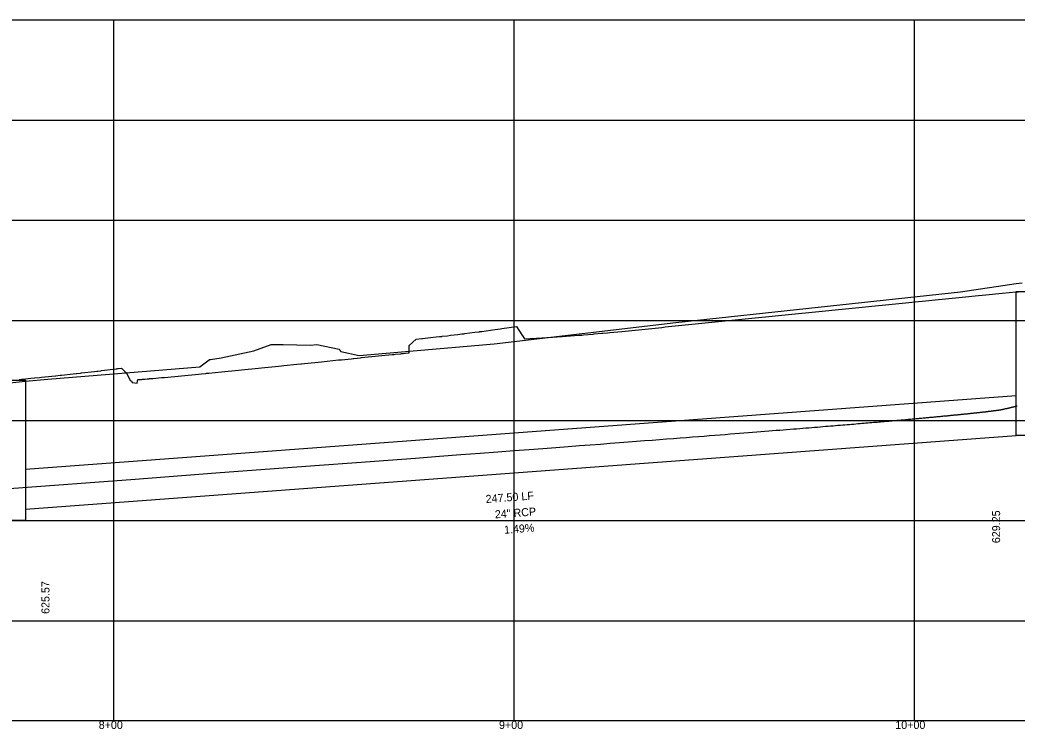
# Model space of a CAD drawing. Extents: x 2254979 to 2278074, y 13790855 to 13792793.
# Drawn here: x 2260737.2 to 2260986.3, y 13792139.4 to 13792316.4 of the extents above; entities that cross this region are included whole.
import ezdxf

# ---------------------------------------------------------------- set-up
doc = ezdxf.new("R2010")
doc.units = 0
for name, color, linetype in [('blank4', 7, 'Continuous'), ('D_DRN_PROF_HGL', 7, 'Continuous'), ('D_PROF_1', 7, 'Continuous'), ('D_PROF_NOTES_1', 7, 'Continuous'), ('Default', 7, 'Continuous'), ('Drain_PipeInside', 7, 'Continuous'), ('E_Terrain', 7, 'Continuous'), ('Inlet', 7, 'Continuous'), ('z - Construction', 7, 'Continuous')]:
    doc.layers.add(name, color=color, linetype=linetype)

msp = doc.modelspace()

# ---------------------------------------------------------------- linework, layer by layer
at = {"layer": 'blank4'}
msp.add_lwpolyline([(2259960.69, 13792141.44), (2259960.69, 13792316.44), (2261351.48, 13792316.44), (2261351.48, 13792141.44)], close=True, dxfattribs=at)
at = {"layer": 'D_DRN_PROF_HGL'}
msp.add_lwpolyline([(2260734.57, 13792199.49), (2260765.97, 13792201.83), (2260786.15, 13792203.34), (2260800.68, 13792204.43), (2260812.02, 13792205.27), (2260821.31, 13792205.97), (2260829.17, 13792206.56), (2260835.98, 13792207.07), (2260841.98, 13792207.52), (2260847.34, 13792207.93), (2260852.18, 13792208.29), (2260856.59, 13792208.63), (2260860.64, 13792208.93), (2260864.38, 13792209.21), (2260867.85, 13792209.48), (2260871.09, 13792209.72), (2260874.13, 13792209.96), (2260876.99, 13792210.17), (2260879.68, 13792210.38), (2260882.23, 13792210.57), (2260884.65, 13792210.76), (2260886.95, 13792210.93), (2260889.14, 13792211.1), (2260891.24, 13792211.26), (2260893.24, 13792211.42), (2260895.16, 13792211.56), (2260897, 13792211.71), (2260898.77, 13792211.84), (2260900.47, 13792211.97), (2260902.11, 13792212.1), (2260903.69, 13792212.22), (2260905.21, 13792212.34), (2260906.69, 13792212.46), (2260908.12, 13792212.57), (2260909.5, 13792212.68), (2260910.84, 13792212.78), (2260912.13, 13792212.88), (2260913.39, 13792212.98), (2260914.62, 13792213.08), (2260915.81, 13792213.17), (2260916.96, 13792213.26), (2260918.09, 13792213.35), (2260919.18, 13792213.44), (2260920.25, 13792213.52), (2260921.29, 13792213.6), (2260922.3, 13792213.68), (2260923.29, 13792213.76), (2260924.26, 13792213.84), (2260925.2, 13792213.91), (2260926.12, 13792213.99), (2260927.02, 13792214.06), (2260927.9, 13792214.13), (2260928.75, 13792214.2), (2260929.6, 13792214.27), (2260930.42, 13792214.33), (2260931.22, 13792214.4), (2260932.01, 13792214.46), (2260932.78, 13792214.52), (2260933.54, 13792214.59), (2260934.28, 13792214.65), (2260935.01, 13792214.7), (2260935.72, 13792214.76), (2260936.42, 13792214.82), (2260937.11, 13792214.88), (2260937.78, 13792214.93), (2260938.44, 13792214.99), (2260939.09, 13792215.04), (2260939.73, 13792215.09), (2260940.35, 13792215.14), (2260940.97, 13792215.19), (2260941.57, 13792215.24), (2260942.17, 13792215.29), (2260942.75, 13792215.34), (2260943.32, 13792215.39), (2260943.89, 13792215.44), (2260944.44, 13792215.48), (2260944.99, 13792215.53), (2260945.53, 13792215.57), (2260946.05, 13792215.62), (2260946.57, 13792215.66), (2260947.08, 13792215.7), (2260947.59, 13792215.75), (2260948.08, 13792215.79), (2260948.57, 13792215.83), (2260949.05, 13792215.87), (2260949.53, 13792215.91), (2260949.99, 13792215.95), (2260950.45, 13792215.99), (2260950.91, 13792216.03), (2260951.35, 13792216.07), (2260951.79, 13792216.1), (2260952.22, 13792216.14), (2260952.65, 13792216.18), (2260953.07, 13792216.21), (2260953.49, 13792216.25), (2260953.9, 13792216.29), (2260954.3, 13792216.32), (2260954.7, 13792216.35), (2260955.09, 13792216.39), (2260955.48, 13792216.42), (2260955.86, 13792216.46), (2260956.24, 13792216.49), (2260956.61, 13792216.52), (2260956.98, 13792216.55), (2260957.34, 13792216.59), (2260957.7, 13792216.62), (2260958.05, 13792216.65), (2260958.4, 13792216.68), (2260958.74, 13792216.71), (2260959.08, 13792216.74), (2260959.42, 13792216.77), (2260959.75, 13792216.8), (2260960.07, 13792216.83), (2260960.4, 13792216.86), (2260960.72, 13792216.89), (2260961.03, 13792216.92), (2260961.34, 13792216.94), (2260961.65, 13792216.97), (2260961.95, 13792217), (2260962.25, 13792217.03), (2260962.55, 13792217.05), (2260962.84, 13792217.08), (2260963.13, 13792217.11), (2260963.41, 13792217.13), (2260963.7, 13792217.16), (2260963.97, 13792217.18), (2260964.25, 13792217.21), (2260964.52, 13792217.24), (2260964.79, 13792217.26), (2260965.06, 13792217.29), (2260965.32, 13792217.31), (2260965.58, 13792217.33), (2260965.84, 13792217.36), (2260966.09, 13792217.38), (2260966.34, 13792217.41), (2260966.59, 13792217.43), (2260966.83, 13792217.45), (2260967.08, 13792217.48), (2260967.32, 13792217.5), (2260967.55, 13792217.52), (2260967.79, 13792217.54), (2260968.02, 13792217.57), (2260968.25, 13792217.59), (2260968.48, 13792217.61), (2260968.7, 13792217.63), (2260968.92, 13792217.65), (2260969.14, 13792217.67), (2260969.36, 13792217.7), (2260969.57, 13792217.72), (2260969.78, 13792217.74), (2260969.99, 13792217.76), (2260970.2, 13792217.78), (2260970.41, 13792217.8), (2260970.61, 13792217.82), (2260970.81, 13792217.84), (2260971.01, 13792217.86), (2260971.21, 13792217.88), (2260971.4, 13792217.9), (2260971.59, 13792217.92), (2260971.79, 13792217.94), (2260971.97, 13792217.96), (2260972.16, 13792217.97), (2260972.35, 13792217.99), (2260972.53, 13792218.01), (2260972.71, 13792218.03), (2260972.89, 13792218.05), (2260973.06, 13792218.07), (2260973.24, 13792218.08), (2260973.41, 13792218.1), (2260973.58, 13792218.12), (2260973.75, 13792218.14), (2260973.92, 13792218.15), (2260974.09, 13792218.17), (2260974.25, 13792218.19), (2260974.41, 13792218.21), (2260974.58, 13792218.22), (2260974.74, 13792218.24), (2260974.89, 13792218.26), (2260975.05, 13792218.27), (2260975.2, 13792218.29), (2260975.36, 13792218.31), (2260975.51, 13792218.32), (2260975.66, 13792218.34), (2260975.81, 13792218.36), (2260975.95, 13792218.37), (2260976.1, 13792218.39), (2260976.24, 13792218.4), (2260976.38, 13792218.42), (2260976.53, 13792218.43), (2260976.66, 13792218.45), (2260976.8, 13792218.46), (2260976.94, 13792218.48), (2260977.07, 13792218.49), (2260977.21, 13792218.51), (2260977.34, 13792218.52), (2260977.47, 13792218.54), (2260977.6, 13792218.55), (2260977.73, 13792218.57), (2260977.86, 13792218.58), (2260977.98, 13792218.6), (2260978.11, 13792218.61), (2260978.23, 13792218.63), (2260978.35, 13792218.64), (2260978.47, 13792218.65), (2260978.59, 13792218.67), (2260978.71, 13792218.68), (2260978.83, 13792218.7), (2260978.95, 13792218.71), (2260979.06, 13792218.72), (2260979.17, 13792218.74), (2260979.29, 13792218.75), (2260979.4, 13792218.76), (2260979.51, 13792218.78), (2260979.62, 13792218.79), (2260979.72, 13792218.8), (2260979.83, 13792218.81), (2260979.94, 13792218.83), (2260980.04, 13792218.84), (2260980.15, 13792218.85), (2260980.25, 13792218.87), (2260980.35, 13792218.88), (2260980.45, 13792218.89), (2260980.55, 13792218.9), (2260980.65, 13792218.92), (2260980.75, 13792218.93), (2260980.84, 13792218.94), (2260980.94, 13792218.95), (2260981.03, 13792218.96), (2260981.13, 13792218.98), (2260981.22, 13792218.99), (2260981.31, 13792219), (2260981.4, 13792219.01), (2260981.49, 13792219.02), (2260981.58, 13792219.03), (2260981.67, 13792219.05), (2260981.75, 13792219.06), (2260981.84, 13792219.07), (2260981.92, 13792219.08), (2260982.01, 13792219.09), (2260982.09, 13792219.1), (2260982.17, 13792219.12), (2260982.26, 13792219.14), (2260982.34, 13792219.16), (2260982.42, 13792219.17), (2260982.5, 13792219.19), (2260982.57, 13792219.21), (2260982.65, 13792219.22), (2260982.73, 13792219.24), (2260982.8, 13792219.25), (2260982.88, 13792219.27), (2260982.95, 13792219.29), (2260983.02, 13792219.3), (2260983.1, 13792219.32), (2260983.17, 13792219.33), (2260983.24, 13792219.35), (2260983.31, 13792219.37), (2260983.38, 13792219.38), (2260983.45, 13792219.4), (2260983.52, 13792219.41), (2260983.58, 13792219.43), (2260983.65, 13792219.44), (2260983.71, 13792219.46), (2260983.78, 13792219.47), (2260983.84, 13792219.48), (2260983.91, 13792219.5), (2260983.97, 13792219.51), (2260984.03, 13792219.53), (2260984.09, 13792219.54), (2260984.15, 13792219.56), (2260984.21, 13792219.57), (2260984.27, 13792219.58), (2260984.33, 13792219.6), (2260984.39, 13792219.61), (2260984.45, 13792219.62), (2260984.5, 13792219.64), (2260984.56, 13792219.65), (2260984.61, 13792219.66), (2260984.67, 13792219.68), (2260984.72, 13792219.69), (2260984.78, 13792219.7), (2260984.83, 13792219.72), (2260984.88, 13792219.73), (2260984.93, 13792219.74), (2260984.98, 13792219.75), (2260985.03, 13792219.77), (2260985.08, 13792219.78), (2260985.13, 13792219.79), (2260985.18, 13792219.8), (2260985.23, 13792219.82), (2260985.27, 13792219.83), (2260985.32, 13792219.84), (2260985.37, 13792219.85), (2260985.41, 13792219.86), (2260985.46, 13792219.87), (2260985.5, 13792219.89), (2260985.54, 13792219.9), (2260985.59, 13792219.91), (2260985.63, 13792219.92), (2260985.67, 13792219.93), (2260985.71, 13792219.94), (2260985.75, 13792219.95), (2260985.79, 13792219.96), (2260985.83, 13792219.98), (2260985.87, 13792219.99), (2260985.91, 13792220), (2260985.95, 13792220.01), (2260985.99, 13792220.02), (2260986.02, 13792220.03), (2260986.06, 13792220.04), (2260986.1, 13792220.05), (2260986.13, 13792220.06), (2260986.17, 13792220.07), (2260986.2, 13792220.08), (2260986.24, 13792220.09), (2260986.27, 13792220.1), (2260986.3, 13792220.11), (2260986.33, 13792220.12)], dxfattribs=at)
at = {"layer": 'D_PROF_1'}
msp.add_lwpolyline([(2260737, 13792226.72), (2260737.57, 13792226.77), (2260738.57, 13792226.87), (2260738.57, 13792226.87), (2260739.93, 13792227), (2260740.85, 13792227.09), (2260740.89, 13792227.09), (2260740.9, 13792227.09), (2260742.12, 13792227.21), (2260742.57, 13792227.26), (2260745.19, 13792227.53), (2260746.08, 13792227.62), (2260746.17, 13792227.63), (2260746.2, 13792227.63), (2260747.23, 13792227.74), (2260747.57, 13792227.77), (2260750.48, 13792228.09), (2260751.28, 13792228.17), (2260751.41, 13792228.19), (2260751.45, 13792228.19), (2260752.34, 13792228.29), (2260752.57, 13792228.32), (2260755.82, 13792228.69), (2260756.42, 13792228.76), (2260756.59, 13792228.78), (2260756.62, 13792228.78), (2260757.43, 13792228.88), (2260757.57, 13792228.89), (2260761.26, 13792229.34), (2260761.49, 13792229.37), (2260761.69, 13792229.39), (2260761.7, 13792229.39), (2260762.54, 13792229.5), (2260762.57, 13792229.5), (2260762.82, 13792229.3), (2260763.43, 13792228.71), (2260763.84, 13792228.31), (2260764.7, 13792226.46), (2260765.06, 13792226.33), (2260765.26, 13792225.94), (2260766.46, 13792225.79), (2260766.47, 13792225.8), (2260766.67, 13792226.64), (2260766.79, 13792226.65), (2260767.53, 13792226.71), (2260767.53, 13792226.71), (2260767.57, 13792226.72), (2260767.59, 13792226.72), (2260767.67, 13792226.72), (2260767.78, 13792226.73), (2260768.43, 13792226.79), (2260768.5, 13792226.8), (2260768.51, 13792226.8), (2260769.02, 13792226.84), (2260769.11, 13792226.85), (2260769.11, 13792226.85), (2260769.15, 13792226.85), (2260769.48, 13792226.88), (2260769.53, 13792226.89), (2260769.54, 13792226.89), (2260769.55, 13792226.89), (2260769.56, 13792226.89), (2260769.68, 13792226.9), (2260769.71, 13792226.9), (2260769.87, 13792226.92), (2260770.03, 13792226.93), (2260770.05, 13792226.93), (2260770.42, 13792226.97), (2260772.57, 13792227.16), (2260773.3, 13792227.22), (2260777.57, 13792227.6), (2260781.84, 13792228.03), (2260782.57, 13792228.1), (2260783.65, 13792228.21), (2260783.84, 13792228.23), (2260784.39, 13792228.28), (2260787.57, 13792228.6), (2260791.83, 13792229.03), (2260792.57, 13792229.11), (2260796.83, 13792229.54), (2260797.57, 13792229.61), (2260801.83, 13792230.04), (2260802.57, 13792230.12), (2260803.14, 13792230.17), (2260806.38, 13792230.5), (2260807.39, 13792230.6), (2260807.57, 13792230.62), (2260808.33, 13792230.7), (2260812.57, 13792231.13), (2260816.81, 13792231.55), (2260817.57, 13792231.63), (2260820.02, 13792231.88), (2260820.46, 13792231.92), (2260820.48, 13792231.92), (2260820.63, 13792231.94), (2260822.28, 13792232.11), (2260822.57, 13792232.14), (2260826.8, 13792232.56), (2260827.57, 13792232.64), (2260830.16, 13792232.9), (2260830.63, 13792232.95), (2260830.68, 13792232.95), (2260830.94, 13792232.98), (2260832.32, 13792233.12), (2260832.57, 13792233.14), (2260832.63, 13792233.15), (2260832.94, 13792233.18), (2260834.23, 13792233.31), (2260834.46, 13792233.33), (2260834.46, 13792233.89), (2260834.46, 13792234.01), (2260834.46, 13792234.31), (2260834.47, 13792235.21), (2260836.18, 13792236.77), (2260837.57, 13792236.91), (2260837.7, 13792236.93), (2260837.79, 13792236.94), (2260839.77, 13792237.15), (2260841.19, 13792237.3), (2260842.02, 13792237.39), (2260842.57, 13792237.45), (2260842.65, 13792237.46), (2260842.7, 13792237.47), (2260843.99, 13792237.62), (2260844.78, 13792237.71), (2260846.6, 13792237.93), (2260847.57, 13792238.05), (2260847.61, 13792238.05), (2260847.63, 13792238.05), (2260848.1, 13792238.11), (2260848.34, 13792238.14), (2260850.85, 13792238.47), (2260851.84, 13792238.6), (2260851.98, 13792238.62), (2260852.03, 13792238.63), (2260852.43, 13792238.68), (2260852.57, 13792238.7), (2260854.72, 13792239), (2260855.27, 13792239.08), (2260857.26, 13792239.37), (2260857.57, 13792239.41), (2260861.27, 13792239.95), (2260862.57, 13792237.85), (2260862.62, 13792237.77), (2260862.63, 13792237.76), (2260863.22, 13792236.81), (2260867.57, 13792237.09), (2260867.7, 13792237.09), (2260869.88, 13792237.23), (2260869.89, 13792237.23), (2260870.07, 13792237.24), (2260870.28, 13792237.26), (2260872.57, 13792237.41), (2260872.65, 13792237.42), (2260873.31, 13792237.46), (2260873.69, 13792237.49), (2260876.81, 13792237.72), (2260876.91, 13792237.73), (2260877.57, 13792237.79), (2260877.96, 13792237.82), (2260880.37, 13792238.02), (2260880.7, 13792238.05), (2260882.57, 13792238.21), (2260882.79, 13792238.23), (2260883.96, 13792238.34), (2260884.54, 13792238.4), (2260887.57, 13792238.69), (2260888.4, 13792238.78), (2260892.57, 13792239.2), (2260896.75, 13792239.62), (2260897.57, 13792239.7), (2260898.4, 13792239.79), (2260902.58, 13792240.21), (2260903.41, 13792240.29), (2260907.58, 13792240.71), (2260911.74, 13792241.13), (2260912.58, 13792241.22), (2260913.42, 13792241.3), (2260917.58, 13792241.72), (2260921.73, 13792242.14), (2260922.58, 13792242.22), (2260923.43, 13792242.31), (2260927.58, 13792242.73), (2260931.72, 13792243.15), (2260932.58, 13792243.23), (2260933.43, 13792243.32), (2260937.58, 13792243.74), (2260941.71, 13792244.16), (2260942.58, 13792244.24), (2260943.44, 13792244.33), (2260947.58, 13792244.75), (2260951.7, 13792245.16), (2260952.58, 13792245.25), (2260953.45, 13792245.34), (2260957.58, 13792245.76), (2260961.69, 13792246.17), (2260962.58, 13792246.26), (2260966.69, 13792246.68), (2260967.58, 13792246.76), (2260968.46, 13792246.85), (2260972.58, 13792247.27), (2260976.68, 13792247.68), (2260977.58, 13792247.77), (2260978.47, 13792247.85), (2260982.58, 13792248.23), (2260986.08, 13792248.54), (2260986.08, 13792248.54), (2260986.67, 13792248.6)], dxfattribs=at)
at = {"layer": 'Default'}
for p, q in [((2260760.69, 13792141.44), (2260760.69, 13792316.44)), ((2260860.69, 13792141.44), (2260860.69, 13792316.44)), ((2260960.69, 13792141.44), (2260960.69, 13792316.44))]:
    msp.add_line(p, q, dxfattribs=at)
at = {"layer": 'Drain_PipeInside'}
for p, q in [((2260738.57, 13792204.28), (2260986.08, 13792222.69)), ((2260738.57, 13792194.28), (2260986.08, 13792212.69))]:
    msp.add_line(p, q, dxfattribs=at)
at = {"layer": 'E_Terrain'}
msp.add_lwpolyline([(2260734.57, 13792225.81), (2260738.57, 13792226.23), (2260738.57, 13792226.23), (2260744.13, 13792226.79), (2260782.15, 13792229.85), (2260784.48, 13792231.58), (2260784.54, 13792231.64), (2260784.81, 13792231.64), (2260787.49, 13792232.12), (2260795.65, 13792233.87), (2260799.93, 13792235.4), (2260802.97, 13792235.41), (2260809.82, 13792235.24), (2260811.39, 13792235.46), (2260816.96, 13792234.25), (2260817.08, 13792234.11), (2260817.08, 13792234.11), (2260817.23, 13792233.86), (2260817.36, 13792233.66), (2260821.98, 13792232.69), (2260855.66, 13792235.55), (2260901.09, 13792240.94), (2260972.19, 13792248.59), (2260986.08, 13792250.62), (2260986.08, 13792250.62), (2260987.58, 13792250.84)], dxfattribs=at)
at = {"layer": 'Inlet'}
for points in [[(2260986.08, 13792248.68), (2260989.08, 13792248.68), (2260989.08, 13792212.69), (2260986.08, 13792212.69)], [(2260730.57, 13792226.5), (2260738.57, 13792226.5), (2260738.57, 13792191.44), (2260730.57, 13792191.44)]]:
    msp.add_lwpolyline(points, close=True, dxfattribs=at)
at = {"layer": 'z - Construction'}
for p, q in [((2259960.69, 13792291.44), (2261351.48, 13792291.44)), ((2259960.69, 13792266.44), (2261351.48, 13792266.44)), ((2259960.69, 13792241.44), (2261351.48, 13792241.44)), ((2259960.69, 13792216.44), (2261351.48, 13792216.44)), ((2259960.69, 13792191.44), (2261351.48, 13792191.44)), ((2259960.69, 13792166.44), (2261351.48, 13792166.44))]:
    msp.add_line(p, q, dxfattribs=at)

# ---------------------------------------------------------------- texts
at = {"layer": 'D_PROF_NOTES_1'}
for s, rotation, p in [('247.50 LF', 4.2551, (2260853.63, 13792195.84)), ('24" RCP', 4.2551, (2260855.92, 13792192)), ('629.25', 90, (2260982.08, 13792185.82)), ('1.49%', 4.2551, (2260858.22, 13792188.16)), ('625.57', 90, (2260744.57, 13792168.16))]:
    msp.add_text(s, height=2, rotation=rotation, dxfattribs=at).set_placement(p)
at = {"layer": 'Default'}
for s, p in [('8+00', (2260756.88, 13792139.44)), ('9+00', (2260856.88, 13792139.44)), ('10+00', (2260955.89, 13792139.44))]:
    msp.add_text(s, height=2, dxfattribs=at).set_placement(p)

doc.saveas('drawing.dxf')
